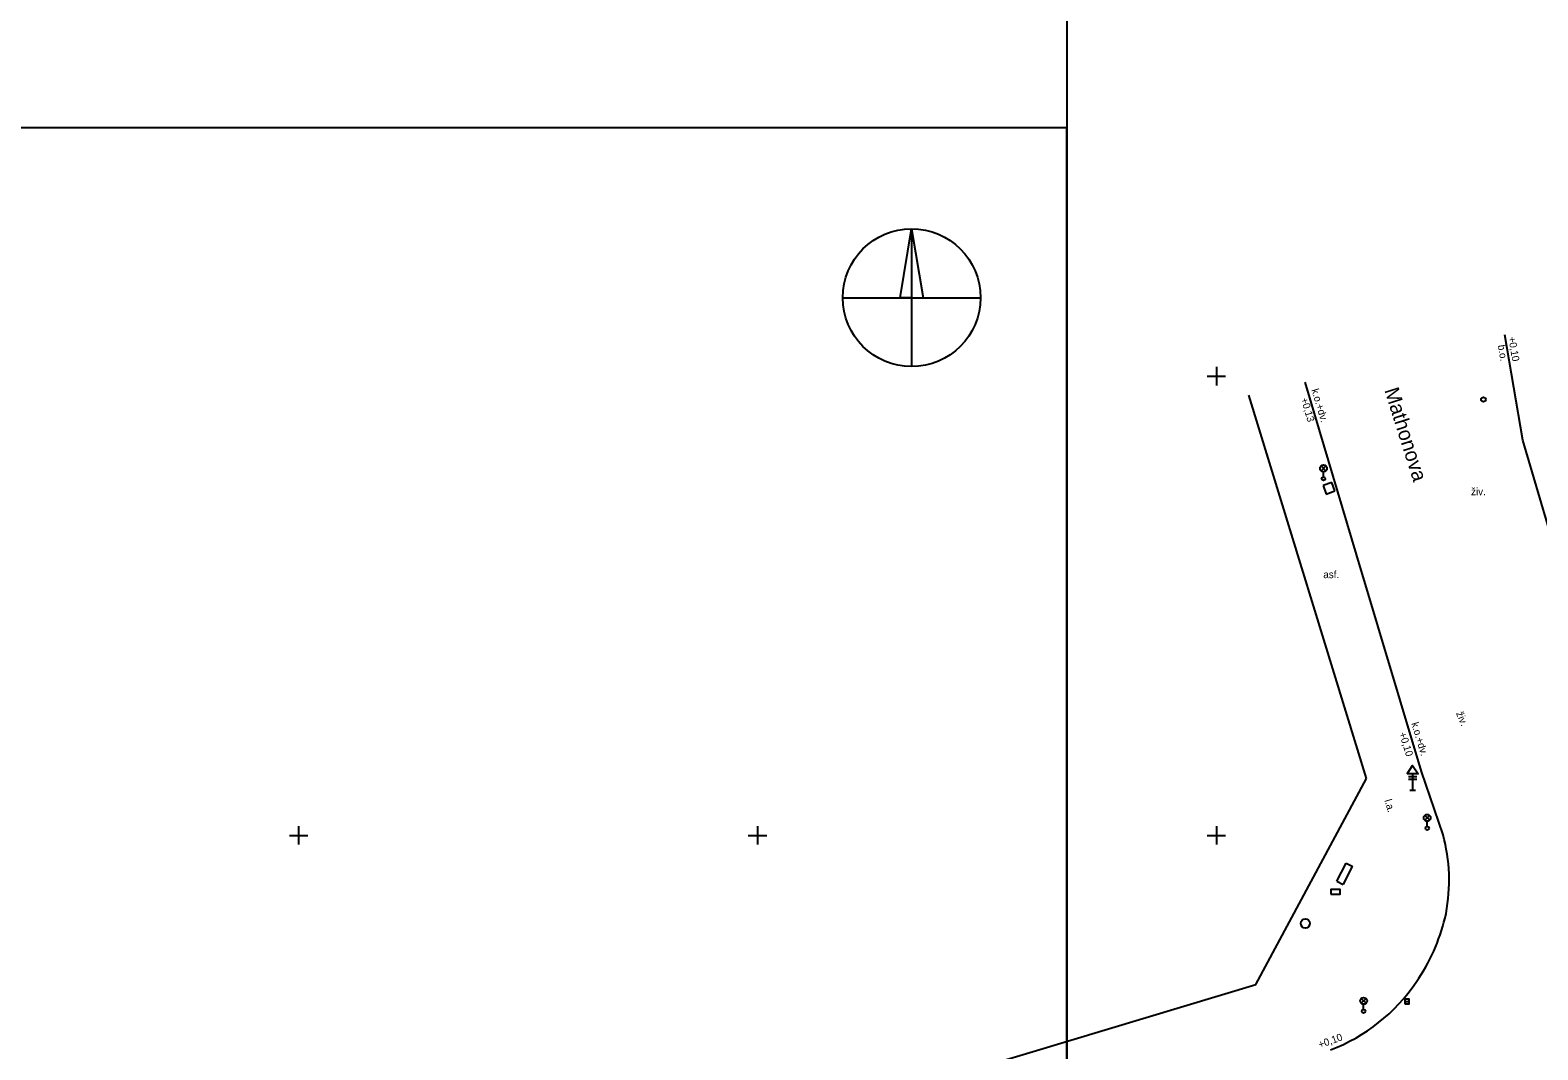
# Model space of a CAD drawing. Extents: x -597333 to -596488, y -1158921 to -1158644.
# Drawn here: x -596964.6 to -596882.5, y -1158761.7 to -1158706.2 of the extents above; entities that cross this region are included whole.
import ezdxf

# ---------------------------------------------------------------- set-up
doc = ezdxf.new("R2010")
doc.units = 0
for name, color, linetype in [('Vrstva 1', 7, 'Continuous'), ('Vrstva 10', 7, 'Continuous'), ('Vrstva 23', 7, 'Continuous'), ('Vrstva 24', 7, 'Continuous'), ('Vrstva 25', 7, 'Continuous'), ('Vrstva 29', 7, 'Continuous'), ('Vrstva 42', 7, 'Continuous'), ('Vrstva 44', 7, 'Continuous'), ('Vrstva 49', 7, 'Continuous'), ('Vrstva 50', 7, 'Continuous'), ('Vrstva 52', 7, 'Continuous'), ('Vrstva 62', 7, 'Continuous'), ('Vrstva 7', 7, 'Continuous')]:
    doc.layers.add(name, color=color, linetype=linetype)

msp = doc.modelspace()

# ---------------------------------------------------------------- linework, layer by layer
at = {"layer": 'Vrstva 1'}
msp.add_lwpolyline([(-596908.148, -1158651.282), (-596908.148, -1158799.157), (-596698.148, -1158799.157), (-596698.148, -1158650.657), (-596905.25, -1158650.657)], dxfattribs=at)
msp.add_lwpolyline([(-597118.148, -1158711.476), (-597118.148, -1158859.976), (-596908.148, -1158859.976), (-596908.148, -1158711.476)], close=True, dxfattribs=at)
at = {"layer": 'Vrstva 10'}
for p, q in [((-596891.828, -1158746.892), (-596898.23, -1158726.04)), ((-596897.848, -1158758.106), (-596891.828, -1158746.892))]:
    msp.add_line(p, q, dxfattribs=at)
msp.add_lwpolyline([(-596923.409, -1158765.799), (-596909.992, -1158761.761), (-596897.848, -1158758.106)], dxfattribs=at)
at = {"layer": 'Vrstva 23'}
for p, q in [((-596893.722, -1158730.779), (-596894.191, -1158730.952)), ((-596894.191, -1158730.952), (-596894.018, -1158731.421)), ((-596893.549, -1158731.248), (-596893.722, -1158730.779)), ((-596894.018, -1158731.421), (-596893.549, -1158731.248)), ((-596893.438, -1158752.495), (-596892.939, -1158751.513)), ((-596893.438, -1158752.495), (-596893.105, -1158752.664))]:
    msp.add_line(p, q, dxfattribs=at)
msp.add_lwpolyline([(-596892.939, -1158751.513), (-596892.609, -1158751.681), (-596893.105, -1158752.664)], dxfattribs=at)
at = {"layer": 'Vrstva 24'}
msp.add_circle((-596885.46, -1158726.27), 0.125, dxfattribs=at)
at = {"layer": 'Vrstva 25'}
msp.add_line((-596889.746, -1158759.044), (-596889.496, -1158759.044), dxfattribs=at)
msp.add_lwpolyline([(-596889.746, -1158759.169), (-596889.496, -1158759.169), (-596889.496, -1158758.919), (-596889.746, -1158758.919)], close=True, dxfattribs=at)
msp.add_circle((-596895.158, -1158754.791), 0.25, dxfattribs=at)
at = {"layer": 'Vrstva 29'}
for p, q in [((-596894.302, -1158730.149), (-596894.038, -1158729.885)), ((-596894.034, -1158730.148), (-596894.298, -1158729.883)), ((-596894.17, -1158730.48), (-596894.17, -1158730.205)), ((-596888.655, -1158749.174), (-596888.391, -1158748.91)), ((-596888.387, -1158749.173), (-596888.651, -1158748.908)), ((-596888.523, -1158749.505), (-596888.523, -1158749.23)), ((-596892.116, -1158759.137), (-596891.852, -1158758.873)), ((-596891.848, -1158759.136), (-596892.112, -1158758.871)), ((-596891.984, -1158759.468), (-596891.984, -1158759.193))]:
    msp.add_line(p, q, dxfattribs=at)
msp.add_lwpolyline([(-596893.771, -1158753.195), (-596893.271, -1158753.195), (-596893.271, -1158752.945), (-596893.771, -1158752.945)], close=True, dxfattribs=at)
for centre, radius in [((-596894.17, -1158730.018), 0.188), ((-596894.17, -1158730.58), 0.1), ((-596888.523, -1158749.042), 0.188), ((-596888.523, -1158749.605), 0.1), ((-596891.984, -1158759.005), 0.188), ((-596891.984, -1158759.568), 0.1)]:
    msp.add_circle(centre, radius, dxfattribs=at)
at = {"layer": 'Vrstva 44'}
for p, q in [((-596889.314, -1158746.635), (-596889.314, -1158747.535)), ((-596889.534, -1158746.785), (-596889.086, -1158746.785)), ((-596889.534, -1158746.935), (-596889.091, -1158746.935)), ((-596889.464, -1158747.535), (-596889.164, -1158747.535))]:
    msp.add_line(p, q, dxfattribs=at)
msp.add_lwpolyline([(-596889.614, -1158746.64), (-596889.314, -1158746.185), (-596889.014, -1158746.64)], close=True, dxfattribs=at)
at = {"layer": 'Vrstva 52'}
for p, q in [((-596916.605, -1158716.977), (-596915.98, -1158720.727)), ((-596920.355, -1158720.727), (-596912.855, -1158720.727)), ((-596916.605, -1158720.727), (-596916.605, -1158724.477))]:
    msp.add_line(p, q, dxfattribs=at)
msp.add_lwpolyline([(-596916.605, -1158716.977), (-596916.605, -1158720.727), (-596917.23, -1158720.727)], close=True, dxfattribs=at)
msp.add_circle((-596916.605, -1158720.727), 3.75, dxfattribs=at)
at = {"layer": 'Vrstva 62'}
for p, q in [((-596900, -1158724.5), (-596900, -1158725.5)), ((-596900.5, -1158725), (-596899.5, -1158725)), ((-596950.5, -1158750), (-596949.5, -1158750)), ((-596950, -1158749.5), (-596950, -1158750.5)), ((-596925.5, -1158750), (-596924.5, -1158750)), ((-596925, -1158749.5), (-596925, -1158750.5)), ((-596900.5, -1158750), (-596899.5, -1158750)), ((-596900, -1158749.5), (-596900, -1158750.5))]:
    msp.add_line(p, q, dxfattribs=at)
at = {"layer": 'Vrstva 7'}
msp.add_line((-596887.66, -1158749.96), (-596888.83, -1158746.52), dxfattribs=at)
for points in [[(-596879.16, -1158742.42), (-596879.92, -1158739.94), (-596881.04, -1158736.18), (-596883.32, -1158728.49), (-596884.3, -1158722.75)], [(-596888.83, -1158746.52), (-596892.37, -1158734.7), (-596895.16, -1158725.32)]]:
    msp.add_lwpolyline(points, dxfattribs=at)
for centre, radius, start, end in [((-596896.791, -1158752.453), 9.465, 349.08943, 15.26851), ((-596897.742, -1158752.04), 10.479, 326.80287, 347.86073), ((-596897.288, -1158752.421), 9.89, 290.73413, 325.71241), ((-596898.242, -1158751.726), 11.07, 325.51744, 326.85678)]:
    msp.add_arc(centre, radius, start, end, dxfattribs=at)

# ---------------------------------------------------------------- texts
at = {"layer": 'Vrstva 42'}
msp.add_text('Mathonova', height=0.8, rotation=287.59623, dxfattribs=at).set_placement((-596890.864, -1158725.758))
at = {"layer": 'Vrstva 49'}
for s, rotation, p in [('b.o.', 279.68879, (-596884.678, -1158723.324)), ('k.o.+dv.', 286.56466, (-596894.832, -1158725.747)), ('živ.', 292.5662, (-596886.959, -1158743.348)), ('k.o.+dv.', 286.67256, (-596889.391, -1158743.901)), ('l.a.', 286.92669, (-596890.853, -1158748.094))]:
    msp.add_text(s, height=0.4, rotation=rotation, dxfattribs=at).set_placement(p)
for s, p in [('živ.', (-596886.131, -1158731.479)), ('asf.', (-596894.179, -1158735.994))]:
    msp.add_text(s, height=0.4, dxfattribs=at).set_placement(p)
at = {"layer": 'Vrstva 50'}
for s, rotation, p in [('+0,10', 279.68879, (-596884.108, -1158722.884)), ('+0,13', 286.56466, (-596895.412, -1158726.232)), ('+0,10', 287.53939, (-596890.062, -1158744.448)), ('+0,10', 19.6818, (-596894.37, -1158761.594))]:
    msp.add_text(s, height=0.4, rotation=rotation, dxfattribs=at).set_placement(p)

doc.saveas('drawing.dxf')
